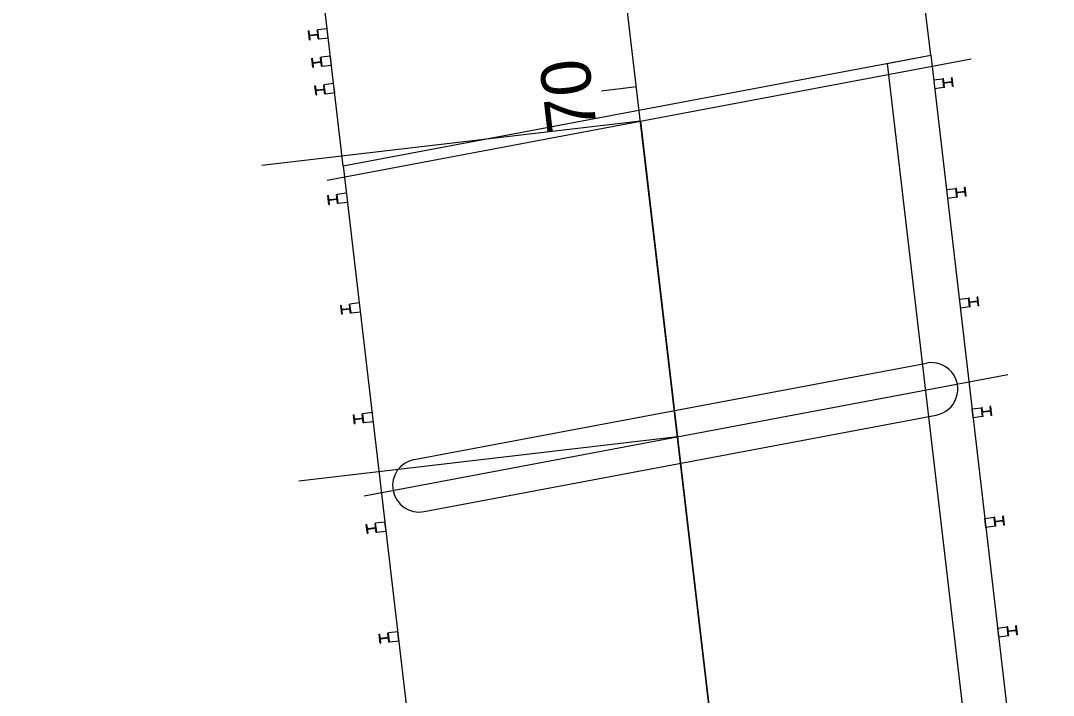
# Model space of a CAD drawing. Extents: x 27625 to 127752, y 6088 to 302357.
# Drawn here: x 127691.7 to 127750.2, y 302023.2 to 302061.4 of the extents above; entities that cross this region are included whole.
import ezdxf

# ---------------------------------------------------------------- set-up
doc = ezdxf.new("R2010")
doc.units = 0
for name, color, linetype in [('_CIVIL_CONSTRUCTION', 7, 'Continuous'), ('DR_X_Cells', 7, 'Continuous'), ('DV_X_Property_Line', 7, 'Continuous'), ('DV_X_Section_VMS_Line', 7, 'Continuous'), ('RW_X_CL', 7, 'Continuous'), ('RW_X_CL_100_Bearings', 7, 'Continuous'), ('RW_X_CL_100_Curve_Data', 7, 'Continuous'), ('RW_X_CL_100_Stations', 7, 'Continuous'), ('RW_X_Fee_RW', 7, 'Continuous'), ('SC_Scratch13', 7, 'Continuous'), ('TopoDOT_Transients', 7, 'Continuous')]:
    doc.layers.add(name, color=color, linetype=linetype)

msp = doc.modelspace()

# ---------------------------------------------------------------- linework, layer by layer
at = {"layer": '_CIVIL_CONSTRUCTION'}
for p, q in [((127726.789, 302055.717), (127705.362, 302053.211)), ((127728.88, 302037.839), (127707.454, 302035.333))]:
    msp.add_line(p, q, dxfattribs=at)
at = {"layer": 'DR_X_Cells'}
msp.add_line((127726.562, 302057.655), (127724.576, 302057.422), dxfattribs=at)
msp.add_line((127726.562, 302057.655), (127724.576, 302057.422), dxfattribs=at)
at = {"layer": 'DV_X_Property_Line'}
for p, q in [((127743.217, 302059.446), (127750.158, 302000.104)), ((127709.97, 302053.181), (127716.911, 301993.839))]:
    msp.add_line(p, q, dxfattribs=at)
at = {"layer": 'DV_X_Section_VMS_Line'}
msp.add_line((127726.789, 302055.717), (127735.28, 301983.124), dxfattribs=at)
at = {"layer": 'RW_X_CL'}
for p, q in [((127713.986, 302036.559), (127742.972, 302042.021)), ((127714.542, 302033.611), (127743.527, 302039.073))]:
    msp.add_line(p, q, dxfattribs=at)
for centre, start, end in [((127743.25, 302040.547), 280.67141, 100.67141), ((127714.264, 302035.085), 100.67141, 280.67141)]:
    msp.add_arc(centre, 1.5, start, end, dxfattribs=at)
at = {"layer": 'RW_X_CL_100_Bearings'}
for p, q in [((127743.217, 302059.446), (127741.474, 302074.344)), ((127709.97, 302053.181), (127708.227, 302068.079)), ((127709.97, 302053.181), (127743.217, 302059.446))]:
    msp.add_line(p, q, dxfattribs=at)
at = {"layer": 'RW_X_CL_100_Curve_Data'}
for p, q in [((127708.006, 302060.82), (127708.043, 302060.825)), ((127708.066, 302060.314), (127708.006, 302060.82)), ((127708.067, 302060.618), (127708.043, 302060.825)), ((127708.101, 302060.59), (127708.495, 302060.636)), ((127708.105, 302060.559), (127708.498, 302060.605)), ((127708.498, 302060.878), (127708.534, 302060.882)), ((127708.522, 302060.671), (127708.498, 302060.878)), ((127708.557, 302060.371), (127708.533, 302060.578)), ((127709.062, 302060.944), (127708.534, 302060.882)), ((127708.593, 302060.375), (127708.534, 302060.882)), ((127708.066, 302060.314), (127708.102, 302060.318)), ((127708.102, 302060.318), (127708.078, 302060.525)), ((127708.557, 302060.371), (127708.593, 302060.375)), ((127708.593, 302060.375), (127709.121, 302060.437)), ((127709.243, 302059.392), (127708.715, 302059.33)), ((127708.188, 302059.269), (127708.224, 302059.273)), ((127708.247, 302058.762), (127708.188, 302059.269)), ((127708.248, 302059.066), (127708.224, 302059.273)), ((127708.283, 302058.766), (127708.259, 302058.973)), ((127708.283, 302059.039), (127708.676, 302059.085)), ((127708.286, 302059.007), (127708.68, 302059.053)), ((127708.679, 302059.326), (127708.715, 302059.33)), ((127708.704, 302059.119), (127708.679, 302059.326)), ((127708.739, 302058.819), (127708.714, 302059.026)), ((127708.775, 302058.823), (127708.715, 302059.33)), ((127708.739, 302058.819), (127708.775, 302058.823)), ((127708.775, 302058.823), (127709.302, 302058.885)), ((127708.247, 302058.762), (127708.283, 302058.766)), ((127708.369, 302057.717), (127708.406, 302057.721)), ((127708.429, 302057.21), (127708.369, 302057.717)), ((127708.43, 302057.514), (127708.406, 302057.721)), ((127708.861, 302057.774), (127708.897, 302057.778)), ((127708.885, 302057.567), (127708.861, 302057.774)), ((127709.425, 302057.84), (127708.897, 302057.778)), ((127708.956, 302057.271), (127708.897, 302057.778)), ((127743.379, 302058.056), (127743.907, 302058.118)), ((127743.943, 302058.122), (127743.907, 302058.118)), ((127743.966, 302057.611), (127743.907, 302058.118)), ((127743.967, 302057.915), (127743.943, 302058.122)), ((127744.002, 302057.615), (127743.978, 302057.822)), ((127744.395, 302057.934), (127744.002, 302057.888)), ((127744.399, 302057.903), (127744.006, 302057.857)), ((127744.435, 302058.18), (127744.398, 302058.175)), ((127744.423, 302057.968), (127744.398, 302058.175)), ((127744.458, 302057.669), (127744.433, 302057.875)), ((127744.494, 302057.673), (127744.435, 302058.18)), ((127744.494, 302057.673), (127744.458, 302057.669)), ((127708.429, 302057.21), (127708.465, 302057.214)), ((127708.465, 302057.214), (127708.441, 302057.421)), ((127708.464, 302057.487), (127708.858, 302057.533)), ((127708.468, 302057.455), (127708.861, 302057.501)), ((127708.92, 302057.267), (127708.896, 302057.474)), ((127708.92, 302057.267), (127708.956, 302057.271)), ((127708.956, 302057.271), (127709.484, 302057.333)), ((127743.966, 302057.611), (127743.439, 302057.549)), ((127744.002, 302057.615), (127743.966, 302057.611)), ((127744.105, 302051.849), (127744.633, 302051.91)), ((127744.669, 302051.914), (127744.633, 302051.91)), ((127744.692, 302051.403), (127744.633, 302051.91)), ((127744.693, 302051.708), (127744.669, 302051.914)), ((127745.161, 302051.972), (127745.124, 302051.968)), ((127745.149, 302051.761), (127745.124, 302051.968)), ((127745.22, 302051.465), (127745.161, 302051.972)), ((127709.096, 302051.509), (127709.132, 302051.513)), ((127709.155, 302051.002), (127709.096, 302051.509)), ((127709.156, 302051.306), (127709.132, 302051.513)), ((127709.191, 302051.006), (127709.167, 302051.213)), ((127709.19, 302051.279), (127709.584, 302051.325)), ((127709.194, 302051.248), (127709.587, 302051.294)), ((127709.587, 302051.566), (127709.623, 302051.571)), ((127709.611, 302051.36), (127709.587, 302051.566)), ((127709.646, 302051.06), (127709.622, 302051.266)), ((127710.151, 302051.632), (127709.623, 302051.571)), ((127709.682, 302051.064), (127709.623, 302051.571)), ((127744.692, 302051.403), (127744.165, 302051.342)), ((127744.728, 302051.408), (127744.692, 302051.403)), ((127744.728, 302051.408), (127744.704, 302051.615)), ((127745.121, 302051.726), (127744.728, 302051.68)), ((127745.125, 302051.695), (127744.732, 302051.649)), ((127745.184, 302051.461), (127745.16, 302051.668)), ((127745.22, 302051.465), (127745.184, 302051.461)), ((127709.155, 302051.002), (127709.191, 302051.006)), ((127709.646, 302051.06), (127709.682, 302051.064)), ((127709.682, 302051.064), (127710.21, 302051.125)), ((127710.313, 302045.359), (127710.349, 302045.363)), ((127710.337, 302045.152), (127710.313, 302045.359)), ((127710.877, 302045.425), (127710.349, 302045.363)), ((127710.408, 302044.856), (127710.349, 302045.363)), ((127744.832, 302045.641), (127745.359, 302045.703)), ((127745.395, 302045.707), (127745.359, 302045.703)), ((127745.418, 302045.196), (127745.359, 302045.703)), ((127745.42, 302045.5), (127745.395, 302045.707)), ((127745.455, 302045.2), (127745.43, 302045.407)), ((127745.847, 302045.519), (127745.454, 302045.473)), ((127745.851, 302045.487), (127745.458, 302045.441)), ((127745.887, 302045.764), (127745.851, 302045.76)), ((127745.875, 302045.553), (127745.851, 302045.76)), ((127745.91, 302045.253), (127745.886, 302045.46)), ((127745.946, 302045.257), (127745.887, 302045.764)), ((127709.822, 302045.301), (127709.858, 302045.306)), ((127709.881, 302044.794), (127709.822, 302045.301)), ((127709.882, 302045.099), (127709.858, 302045.306)), ((127709.881, 302044.794), (127709.917, 302044.799)), ((127709.917, 302044.799), (127709.893, 302045.006)), ((127709.917, 302045.071), (127710.31, 302045.117)), ((127709.92, 302045.04), (127710.314, 302045.086)), ((127710.372, 302044.852), (127710.348, 302045.059)), ((127710.372, 302044.852), (127710.408, 302044.856)), ((127710.408, 302044.856), (127710.936, 302044.918)), ((127745.418, 302045.196), (127744.891, 302045.134)), ((127745.455, 302045.2), (127745.418, 302045.196)), ((127745.946, 302045.257), (127745.91, 302045.253)), ((127746.613, 302039.557), (127746.577, 302039.552)), ((127746.601, 302039.345), (127746.577, 302039.552)), ((127746.672, 302039.05), (127746.613, 302039.557)), ((127710.548, 302039.094), (127710.584, 302039.098)), ((127710.607, 302038.587), (127710.548, 302039.094)), ((127710.608, 302038.891), (127710.584, 302039.098)), ((127711.039, 302039.151), (127711.075, 302039.155)), ((127711.063, 302038.944), (127711.039, 302039.151)), ((127711.603, 302039.217), (127711.075, 302039.155)), ((127711.135, 302038.648), (127711.075, 302039.155)), ((127745.558, 302039.433), (127746.085, 302039.495)), ((127746.145, 302038.988), (127745.617, 302038.926)), ((127746.121, 302039.499), (127746.085, 302039.495)), ((127746.145, 302038.988), (127746.085, 302039.495)), ((127746.146, 302039.292), (127746.121, 302039.499)), ((127746.181, 302038.992), (127746.145, 302038.988)), ((127746.181, 302038.992), (127746.156, 302039.199)), ((127746.573, 302039.311), (127746.18, 302039.265)), ((127746.577, 302039.28), (127746.184, 302039.234)), ((127746.636, 302039.045), (127746.612, 302039.252)), ((127746.672, 302039.05), (127746.636, 302039.045)), ((127710.607, 302038.587), (127710.643, 302038.591)), ((127710.643, 302038.591), (127710.619, 302038.798)), ((127710.643, 302038.864), (127711.036, 302038.91)), ((127710.646, 302038.832), (127711.04, 302038.878)), ((127711.098, 302038.644), (127711.074, 302038.851)), ((127711.098, 302038.644), (127711.135, 302038.648)), ((127711.135, 302038.648), (127711.662, 302038.71)), ((127746.284, 302033.225), (127746.811, 302033.287)), ((127746.847, 302033.291), (127746.811, 302033.287)), ((127746.871, 302032.78), (127746.811, 302033.287)), ((127746.872, 302033.085), (127746.847, 302033.291)), ((127747.3, 302033.103), (127746.906, 302033.057)), ((127747.339, 302033.349), (127747.303, 302033.345)), ((127747.327, 302033.138), (127747.303, 302033.345)), ((127747.398, 302032.842), (127747.339, 302033.349)), ((127711.274, 302032.886), (127711.31, 302032.89)), ((127711.333, 302032.379), (127711.274, 302032.886)), ((127711.334, 302032.683), (127711.31, 302032.89)), ((127711.369, 302032.383), (127711.345, 302032.59)), ((127711.369, 302032.656), (127711.762, 302032.702)), ((127711.372, 302032.625), (127711.766, 302032.671)), ((127711.765, 302032.943), (127711.801, 302032.948)), ((127711.789, 302032.736), (127711.765, 302032.943)), ((127711.824, 302032.437), (127711.8, 302032.643)), ((127712.329, 302033.009), (127711.801, 302032.948)), ((127711.861, 302032.441), (127711.801, 302032.948)), ((127711.861, 302032.441), (127712.388, 302032.502)), ((127746.871, 302032.78), (127746.343, 302032.719)), ((127746.907, 302032.785), (127746.871, 302032.78)), ((127746.907, 302032.785), (127746.883, 302032.991)), ((127747.303, 302033.072), (127746.91, 302033.026)), ((127747.362, 302032.838), (127747.338, 302033.045)), ((127747.398, 302032.842), (127747.362, 302032.838)), ((127711.333, 302032.379), (127711.369, 302032.383)), ((127711.824, 302032.437), (127711.861, 302032.441)), ((127712, 302026.678), (127712.036, 302026.682)), ((127712.059, 302026.171), (127712, 302026.678)), ((127712.06, 302026.476), (127712.036, 302026.682)), ((127712.491, 302026.736), (127712.527, 302026.74)), ((127712.516, 302026.529), (127712.491, 302026.736)), ((127713.055, 302026.802), (127712.527, 302026.74)), ((127712.587, 302026.233), (127712.527, 302026.74)), ((127747.01, 302027.018), (127747.537, 302027.08)), ((127747.574, 302027.084), (127747.537, 302027.08)), ((127747.597, 302026.573), (127747.537, 302027.08)), ((127747.598, 302026.877), (127747.574, 302027.084)), ((127747.633, 302026.577), (127747.609, 302026.784)), ((127748.026, 302026.896), (127747.632, 302026.849)), ((127748.029, 302026.864), (127747.636, 302026.818)), ((127748.065, 302027.141), (127748.029, 302027.137)), ((127748.053, 302026.93), (127748.029, 302027.137)), ((127748.088, 302026.63), (127748.064, 302026.837)), ((127748.124, 302026.634), (127748.065, 302027.141)), ((127712.059, 302026.171), (127712.095, 302026.176)), ((127712.095, 302026.176), (127712.071, 302026.383)), ((127712.095, 302026.448), (127712.488, 302026.494)), ((127712.098, 302026.417), (127712.492, 302026.463)), ((127712.551, 302026.229), (127712.526, 302026.436)), ((127712.551, 302026.229), (127712.587, 302026.233)), ((127712.587, 302026.233), (127713.114, 302026.295)), ((127747.597, 302026.573), (127747.069, 302026.511)), ((127747.633, 302026.577), (127747.597, 302026.573)), ((127748.124, 302026.634), (127748.088, 302026.63))]:
    msp.add_line(p, q, dxfattribs=at)
for centre, start, end in [((127708.098, 302060.621), 186.67141, 276.67141), ((127708.109, 302060.528), 96.67141, 186.67141), ((127708.491, 302060.667), 276.67141, 6.67141), ((127708.502, 302060.574), 6.67141, 96.67141), ((127708.279, 302059.07), 186.67141, 276.67141), ((127708.29, 302058.976), 96.67141, 186.67141), ((127708.673, 302059.116), 276.67141, 6.67141), ((127708.683, 302059.022), 6.67141, 96.67141), ((127743.998, 302057.919), 186.67141, 276.67141), ((127744.009, 302057.826), 96.67141, 186.67141), ((127744.392, 302057.965), 276.67141, 6.67141), ((127744.402, 302057.872), 6.67141, 96.67141), ((127708.461, 302057.518), 186.67141, 276.67141), ((127708.472, 302057.425), 96.67141, 186.67141), ((127708.854, 302057.564), 276.67141, 6.67141), ((127708.865, 302057.471), 6.67141, 96.67141), ((127709.187, 302051.31), 186.67141, 276.67141), ((127709.198, 302051.217), 96.67141, 186.67141), ((127709.58, 302051.356), 276.67141, 6.67141), ((127709.591, 302051.263), 6.67141, 96.67141), ((127744.724, 302051.711), 186.67141, 276.67141), ((127744.735, 302051.618), 96.67141, 186.67141), ((127745.118, 302051.757), 276.67141, 6.67141), ((127745.129, 302051.664), 6.67141, 96.67141), ((127745.45, 302045.504), 186.67141, 276.67141), ((127745.461, 302045.41), 96.67141, 186.67141), ((127745.844, 302045.55), 276.67141, 6.67141), ((127745.855, 302045.456), 6.67141, 96.67141), ((127709.913, 302045.102), 186.67141, 276.67141), ((127709.924, 302045.009), 96.67141, 186.67141), ((127710.306, 302045.148), 276.67141, 6.67141), ((127710.317, 302045.055), 6.67141, 96.67141), ((127711.032, 302038.941), 276.67141, 6.67141), ((127746.177, 302039.296), 186.67141, 276.67141), ((127746.187, 302039.203), 96.67141, 186.67141), ((127746.57, 302039.342), 276.67141, 6.67141), ((127746.581, 302039.249), 6.67141, 96.67141), ((127710.639, 302038.895), 186.67141, 276.67141), ((127710.65, 302038.801), 96.67141, 186.67141), ((127711.043, 302038.847), 6.67141, 96.67141), ((127746.903, 302033.088), 186.67141, 276.67141), ((127747.296, 302033.134), 276.67141, 6.67141), ((127711.365, 302032.687), 186.67141, 276.67141), ((127711.376, 302032.594), 96.67141, 186.67141), ((127711.758, 302032.733), 276.67141, 6.67141), ((127711.769, 302032.64), 6.67141, 96.67141), ((127746.914, 302032.995), 96.67141, 186.67141), ((127747.307, 302033.041), 6.67141, 96.67141), ((127747.629, 302026.881), 186.67141, 276.67141), ((127747.64, 302026.787), 96.67141, 186.67141), ((127748.022, 302026.927), 276.67141, 6.67141), ((127748.033, 302026.833), 6.67141, 96.67141), ((127712.091, 302026.479), 186.67141, 276.67141), ((127712.102, 302026.386), 96.67141, 186.67141), ((127712.485, 302026.525), 276.67141, 6.67141), ((127712.495, 302026.432), 6.67141, 96.67141)]:
    msp.add_arc(centre, 0.0312, start, end, dxfattribs=at)
at = {"layer": 'RW_X_CL_100_Stations'}
for p, q in [((127709.121, 302060.437), (127709.062, 302060.944)), ((127709.302, 302058.885), (127709.243, 302059.392)), ((127709.484, 302057.333), (127709.425, 302057.84)), ((127745.617, 302038.926), (127745.558, 302039.433)), ((127746.343, 302032.719), (127746.284, 302033.225)), ((127712.388, 302032.502), (127712.329, 302033.009)), ((127713.114, 302026.295), (127713.055, 302026.802)), ((127747.069, 302026.511), (127747.01, 302027.018))]:
    msp.add_line(p, q, dxfattribs=at)
at = {"layer": 'RW_X_Fee_RW'}
for p, q in [((127709.06, 302052.377), (127745.5, 302059.243)), ((127711.151, 302034.499), (127747.591, 302041.365))]:
    msp.add_line(p, q, dxfattribs=at)
at = {"layer": 'SC_Scratch13'}
msp.add_line((127732.328, 302008.36), (127691.71, 302355.623), dxfattribs=at)
at = {"layer": 'TopoDOT_Transients'}
for p, q in [((127740.754, 302058.982), (127743.217, 302059.446)), ((127743.217, 302059.446), (127750.158, 302000.104)), ((127740.754, 302058.982), (127747.695, 301999.639))]:
    msp.add_line(p, q, dxfattribs=at)

# ---------------------------------------------------------------- texts
at = {"layer": 'DR_X_Cells'}
msp.add_text('70', height=2.8, rotation=96.67141, dxfattribs=at).set_placement((127724.329, 302055.228))
msp.add_text('70', height=2.8, rotation=96.67141, dxfattribs=at).set_placement((127724.329, 302055.228))

doc.saveas('drawing.dxf')
